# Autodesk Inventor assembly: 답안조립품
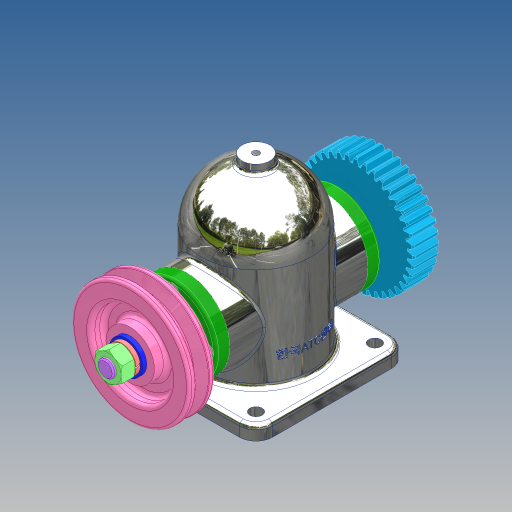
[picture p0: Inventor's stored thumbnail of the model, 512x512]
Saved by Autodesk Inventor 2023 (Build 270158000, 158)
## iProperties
Created: 2025-04
Part Number: 답안조립품
Document SubType Name: Assembly
Designer: Admin
Author: Admin
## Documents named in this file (14)
- C:\Users\Admin\Desktop\750406V1017\답안조립품.iam
- C:\Users\Admin\Desktop\750406V1017\본체.ipt
- C:\Users\Admin\Documents\Inventor\스퍼기어.ipt
- C:\Users\Admin\Desktop\750406V1017\가져온 구성요소\스프링 와셔 M12\스프링 와셔 M12.ipt
- C:\Users\Admin\Desktop\750406V1017\가져온 구성요소\오일 실 26 38 8\오일 실 26 38 8.ipt
- C:\Users\Admin\Desktop\750406V1017\가져온 구성요소\축\축.ipt
- C:\Users\Admin\Desktop\750406V1017\가져온 구성요소\칼라\칼라.ipt
- C:\Users\Admin\Desktop\750406V1017\가져온 구성요소\커버\커버.ipt
- C:\Users\Admin\Desktop\750406V1017\가져온 구성요소\평와셔 M12\평와셔 M12.ipt
- C:\Users\Admin\Desktop\750406V1017\가져온 구성요소\평행 키 5x5x12\평행 키 5x5x12.ipt
- C:\Users\Admin\Desktop\750406V1017\가져온 구성요소\6각 구멍붙이 볼트 M4x12\6각 구멍붙이 볼트 M4x12.ipt
- C:\Users\Admin\Desktop\750406V1017\가져온 구성요소\6각 너트 M12x1\6각 너트 M12x1.ipt
- C:\Users\Admin\Desktop\750406V1017\가져온 구성요소\V 벨트 풀리\V 벨트 풀리.ipt
- C:\Users\Admin\Desktop\750406V1017\가져온 구성요소\깊은 홈 볼 베어링 6203\깊은 홈 볼 베어링 6203.ipt
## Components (11 placed, 3 different names)
1. 6각 너트 M12x1:1
2. V 벨트 풀리:1
3. 6각 너트 M12x1:2
4. 6각 구멍붙이 볼트 M4x12:2
5. 6각 구멍붙이 볼트 M4x12:3
6. 6각 구멍붙이 볼트 M4x12:4
7. 6각 구멍붙이 볼트 M4x12:5
8. 6각 구멍붙이 볼트 M4x12:1
9. 6각 구멍붙이 볼트 M4x12:6
10. 6각 구멍붙이 볼트 M4x12:7
11. 6각 구멍붙이 볼트 M4x12:8
